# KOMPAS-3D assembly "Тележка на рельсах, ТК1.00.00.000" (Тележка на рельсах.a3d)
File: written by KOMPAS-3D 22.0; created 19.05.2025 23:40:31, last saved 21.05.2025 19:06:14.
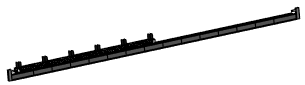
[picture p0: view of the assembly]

Document properties: Автор: user; Полное имя файла: D:\Работа\2025\5. Май\Задание №6 - Тележка для крыши\3Д\Тележка на рельсах.a3d

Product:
- Component [assembly]: Тележка в сборе  | designation ТК1.01.00.000СБ  | qty 1  | pos. 2  | Масса: 103.447138; Форматы листов документа: A3; source file: Тележка в сборе\ТК1.01.00.000 - Тележка в сборе.cdw, Тележка в сборе\ТК1.01.00.000 - Тележка в сборе.spw, Тележка в сборе\Тележка в сборе.a3d
- Component [detail]: Рельс направляющий TBR-C25  | qty 3  | pos. 3  | Масса: 29.607689; Раздел спецификации: Прочие изделия; Примечание: L=3 м; source file: Рельс направляющий TBR-C25.m3d
- Component [assembly]: Рама направляющих  | designation ТК1.02.00.000СБ  | qty 1  | pos. 4  | Масса: 153.815723; Форматы листов документа: A3; source file: Рама направляющих\Рама направляющих.a3d, Рама направляющих\ТК1.02.00.000 - Рама направляющих.spw, Рама направляющих\ТК1.02.00.000 СБ - Рама направляющих Сборочный чертеж.cdw
- Component [detail]: Демпфер  | qty 1  | pos. 7  | Масса: 1.293891; source file: Упор отбойник.m3d
- Component [detail]: Демпфер  | qty 1  | pos. 8  | Масса: 1.293891; source file: Упор отбойник.m3d
- Component [assembly]: Узел монтажный  | designation ТК1.03.00.000СБ  | qty 6  | pos. 10  | Масса: 2.373543; Форматы листов документа: A3; source file: Узел монтажный\Узел монтажный _ ТК1.03.00.000 СБ.cdw, Узел монтажный\Узел монтажный.a3d
- Part/product: Тележка на рельсах  | designation ТК1.00.00.000
    Масса: 362.914968

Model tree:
1. Линейный размер:1  (with: Элемент выдавливания:1, Элемент выдавливания:2)
     Значение = 65
2. Эскиз:1  (with: Операция выдавливания:1)
3. Линейный размер:2  (with: Операция выдавливания:1, Элемент выдавливания:1)
     Значение = 120
4. Линейный размер:5  (with: Элемент выдавливания:1, Элемент выдавливания:6)
     Значение = 89.8579
5. Массив по сетке:3  (with: Элемент выдавливания:1)  (6 pattern instances)
     Шаг 1 = 854; Угол раствора = 90; Шаг 2 = 320
6. Массив по сетке:4  (with: Операция выдавливания:1)  (3 pattern instances)
     Шаг 1 = 3000; Угол раствора = 90
7. Эскиз:2  (with: Операция выдавливания:1, Элемент выдавливания:2, Элемент выдавливания:3, Элемент выдавливания:1, Скругление:2, Элемент выдавливания:8)
     Расстояние = -120; Ориентация = 2; Ориентация = 2; Ориентация = 2

Referenced files in D:\Рабочая папка\АРХИВ\612\05\Задание №6 - Тележка для крыши\3Д\Тележка в сборе\: Тележка в сборе.a3d
Referenced files in D:\Работа\2025\5. Май\Задание №6 - Тележка для крыши\3Д\: Рельс направляющий TBR-C25.m3d, Упор отбойник.m3d
Referenced files in D:\Работа\2025\5. Май\Задание №6 - Тележка для крыши\3Д\Тележка в сборе\: Тележка в сборе.a3d, ТК1.01.00.000 - Тележка в сборе.spw, ТК1.01.00.000 - Тележка в сборе.cdw
Referenced files in D:\Работа\2025\5. Май\Задание №6 - Тележка для крыши\3Д\Рама направляющих\: Рама направляющих.a3d, ТК1.02.00.000 - Рама направляющих.spw, ТК1.02.00.000 СБ - Рама направляющих Сборочный чертеж.cdw
Referenced files in D:\Работа\2025\5. Май\Задание №6 - Тележка для крыши\3Д\Узел монтажный\: Узел монтажный.a3d, Узел монтажный _ ТК1.03.00.000 СБ.cdw
Referenced files in D:\Рабочая папка\АРХИВ\612\05\Задание №6 - Тележка для крыши\3Д\Узел монтажный\: Узел монтажный.a3d
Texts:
  ТК1.01.00.000
  ТК1.01.00.000 СБ
  ТК1.01.00.000       СБ
  ТК1.02.00.000
  ТК1.02.00.000 СБ
  ТК1.02.00.000       СБ
  ТК1.03.00.000
  ТК1.03.00.000 СБ
  ТК1.03.00.000       СБ
  Точка начала. Х
  Точка начала. Y
  Точка начала. Z
  ТК1.00.00.000
  ТК1.01.00.000 Тележка в сборе
  Рельс направляющий TBR-C25 (1)
  ТК1.02.00.000 Рама направляющих
  Демпфер (1)
  Демпфер (2)
  ТК1.03.00.000 Узел монтажный (1)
